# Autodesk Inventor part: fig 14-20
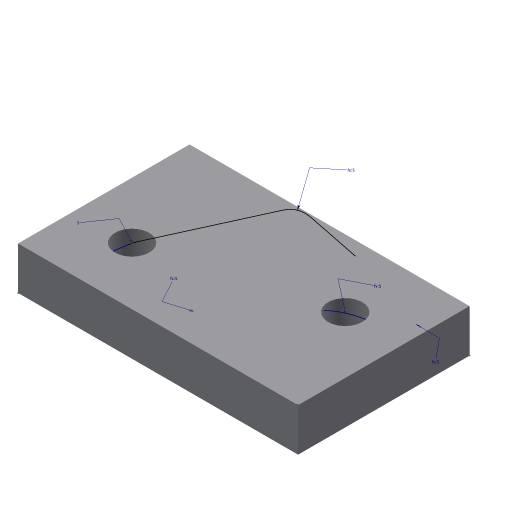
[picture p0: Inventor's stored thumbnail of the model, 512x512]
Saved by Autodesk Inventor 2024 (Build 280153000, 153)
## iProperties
Created: 2005-04
Part Number: fig 14-20
Document SubType Name: Modeling
Designer: CADCIM
Density: 1 g/cm^3
Material: Generic
Appearance: Default
Author: CADCIM
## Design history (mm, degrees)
sketch "Sketch1"
  geometry: L1 (-34.758, -22.218)-(30.545, -22.218); L2 (30.545, -22.218)-(30.545, 17.782); L3 (30.545, 17.782)-(-34.758, 17.782); L4 (-34.758, 17.782)-(-34.758, -22.218)
  constraints: 8 end point, 2 parallel, 1 horizontal, 1 perpendicular
  dimensions: "d0" = 65.30359 distance of L2.end L3.end; "d1" = 40 distance of L1.end L2.end
extrude "Extrusion1" new body sketch "Sketch1" distance "d2" = 10; taper "d3" = 0 deg
hole "Hole1" diameter "d13" = 8; stored, may be unused: countersink angle "d17" = 90 deg, drill point angle "d19" = 118 deg; dims "d11" = 13.458, "d12" = 13.14, "d14" = 6, "d15" = 4, "d16" = 2, "d18" = 15
hole "Hole2" diameter "d22" = 8; stored, may be unused: countersink angle "d26" = 90 deg, drill point angle "d28" = 118 deg; dims "d20" = 13.299, "d21" = 15.705, "d23" = 6, "d24" = 4, "d25" = 2, "d27" = 15
sketch "3D Sketch2" dims "d29" = 5, "d30" = 5 (= d29), "d31" = 5 (= d29), "d32" = 5 (= d29), "d33" = 5 (= d29)
body "Solid1"
other parameters: "LEN" = 1 [user parameter]
